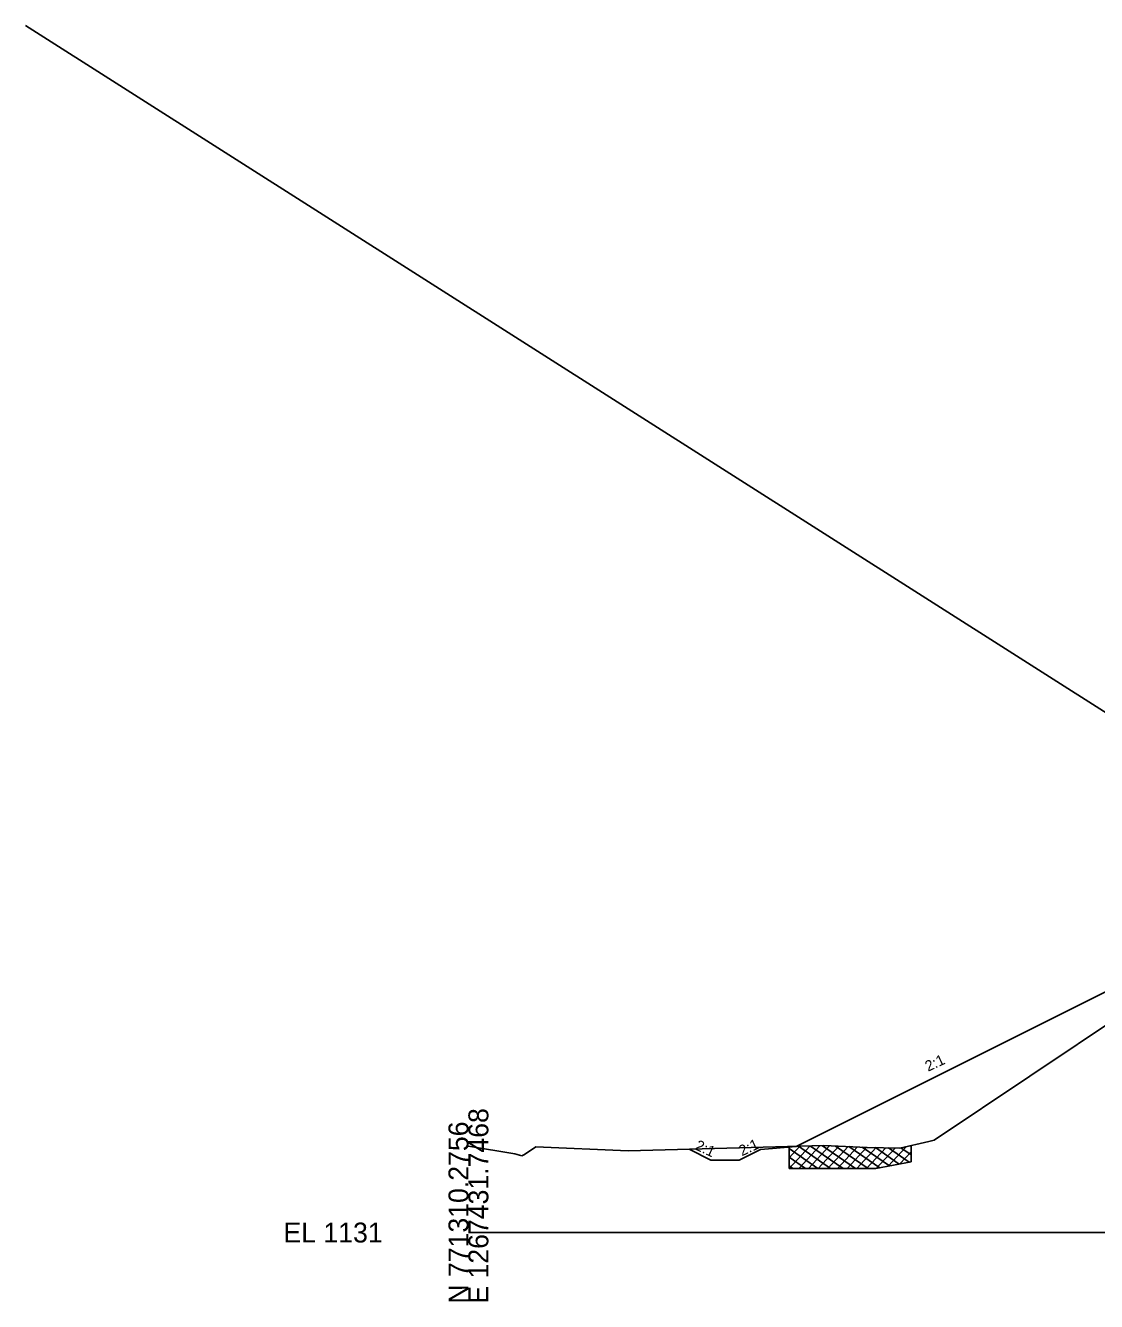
# Model space of a CAD drawing. Extents: x -3833 to 1267678, y -522 to 773248.
# Drawn here: x -62.2 to 88.3, y 7490.3 to 7669.7 of the extents above; entities that cross this region are included whole.
import ezdxf

# ---------------------------------------------------------------- set-up
doc = ezdxf.new("R2010")
doc.units = 0
for name, color, linetype in [('Exist Cross Section Cell', 7, 'Continuous'), ('Exist XS Ground Line', 7, 'Continuous'), ('Prop XS Finish Grade', 7, 'Continuous'), ('Prop XS Label Text', 7, 'Continuous'), ('Prop XS Undercut Exc', 7, 'Continuous'), ('Scratch_Level_1', 7, 'Continuous')]:
    doc.layers.add(name, color=color, linetype=linetype)

msp = doc.modelspace()

# ---------------------------------------------------------------- linework, layer by layer
at = {"layer": 'Exist Cross Section Cell'}
msp.add_line((0, 7500), (150, 7500), dxfattribs=at)
at = {"layer": 'Exist XS Ground Line'}
for p, q in [((65.47, 7512.99), (97.09, 7534.15)), ((0, 7512.14), (6.53, 7511.06)), ((7.86, 7510.96), (9.46, 7512.07)), ((9.46, 7512.07), (22.44, 7511.49)), ((36.31, 7511.84), (49.94, 7512.22)), ((49.94, 7512.22), (56.04, 7511.97)), ((60.65, 7511.87), (64.69, 7512.79)), ((64.69, 7512.79), (65.47, 7512.99)), ((6.53, 7511.06), (7.52, 7510.8)), ((7.52, 7510.8), (7.86, 7510.96)), ((22.44, 7511.49), (36.31, 7511.84)), ((56.04, 7511.97), (60.65, 7511.87))]:
    msp.add_line(p, q, dxfattribs=at)
at = {"layer": 'Prop XS Finish Grade'}
msp.add_line((91.98, 7535.07), (46.06, 7512.11), dxfattribs=at)
msp.add_lwpolyline([(46.06, 7512.11), (41.06, 7511.69), (38.06, 7510.19), (34.06, 7510.19), (31.04, 7511.7)], dxfattribs=at)
at = {"layer": 'Prop XS Undercut Exc'}
for p, q in [((47.98, 7512.16), (45.06, 7509.01)), ((46.58, 7512.12), (45.06, 7510.48)), ((45.06, 7512.08), (45.06, 7509)), ((45.18, 7512.08), (45.06, 7511.95)), ((46.37, 7512.12), (50.9, 7509)), ((49.38, 7512.2), (46.42, 7509)), ((50.73, 7512.18), (47.78, 7509)), ((48.07, 7512.16), (52.66, 7509)), ((52.05, 7512.13), (49.14, 7509)), ((49.76, 7512.21), (54.42, 7509)), ((53.36, 7512.08), (50.51, 7509)), ((51.61, 7512.15), (56.19, 7509)), ((53.48, 7512.08), (57.8, 7509.11)), ((61.53, 7512.07), (59, 7509.33)), ((62.12, 7512.2), (62.24, 7512.12)), ((62.24, 7512.23), (62.24, 7509.95)), ((45.06, 7511.8), (49.13, 7509)), ((45.06, 7510.59), (47.37, 7509)), ((54.68, 7512.03), (51.87, 7509)), ((55.99, 7511.98), (53.23, 7509)), ((57.32, 7511.94), (54.6, 7509)), ((55.35, 7512), (59.18, 7509.37)), ((58.66, 7511.91), (55.96, 7509)), ((57.2, 7511.95), (60.56, 7509.63)), ((59.99, 7511.88), (57.32, 7509)), ((59.02, 7511.9), (61.94, 7509.89)), ((62.24, 7511.36), (60.65, 7509.65)), ((60.79, 7511.9), (62.24, 7510.9)), ((45.06, 7509.37), (45.61, 7509)), ((57.24, 7509), (45.06, 7509)), ((62.24, 7509.95), (57.24, 7509))]:
    msp.add_line(p, q, dxfattribs=at)
at = {"layer": 'Scratch_Level_1'}
msp.add_line((150, 7534.62), (-62.25, 7669.68), dxfattribs=at)

# ---------------------------------------------------------------- texts
at = {"layer": 'Exist Cross Section Cell'}
for s, p in [('E 1267431.7468', (2.8, 7490)), ('N 771310.2756', (0, 7490))]:
    msp.add_text(s, height=2.8, rotation=90, dxfattribs=at).set_placement(p)
msp.add_text('EL 1131', height=2.8, dxfattribs=at).set_placement((-26, 7498.6))
at = {"layer": 'Prop XS Label Text'}
for rotation, p in [(24.9367, (64.6, 7522.59)), (335.0633, (31.72, 7511.73)), (24.9367, (38.44, 7510.71))]:
    msp.add_text('2:1', height=1.5, rotation=rotation, dxfattribs=at).set_placement(p)

doc.saveas('drawing.dxf')
